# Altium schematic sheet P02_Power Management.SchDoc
size 386 x 246 mm
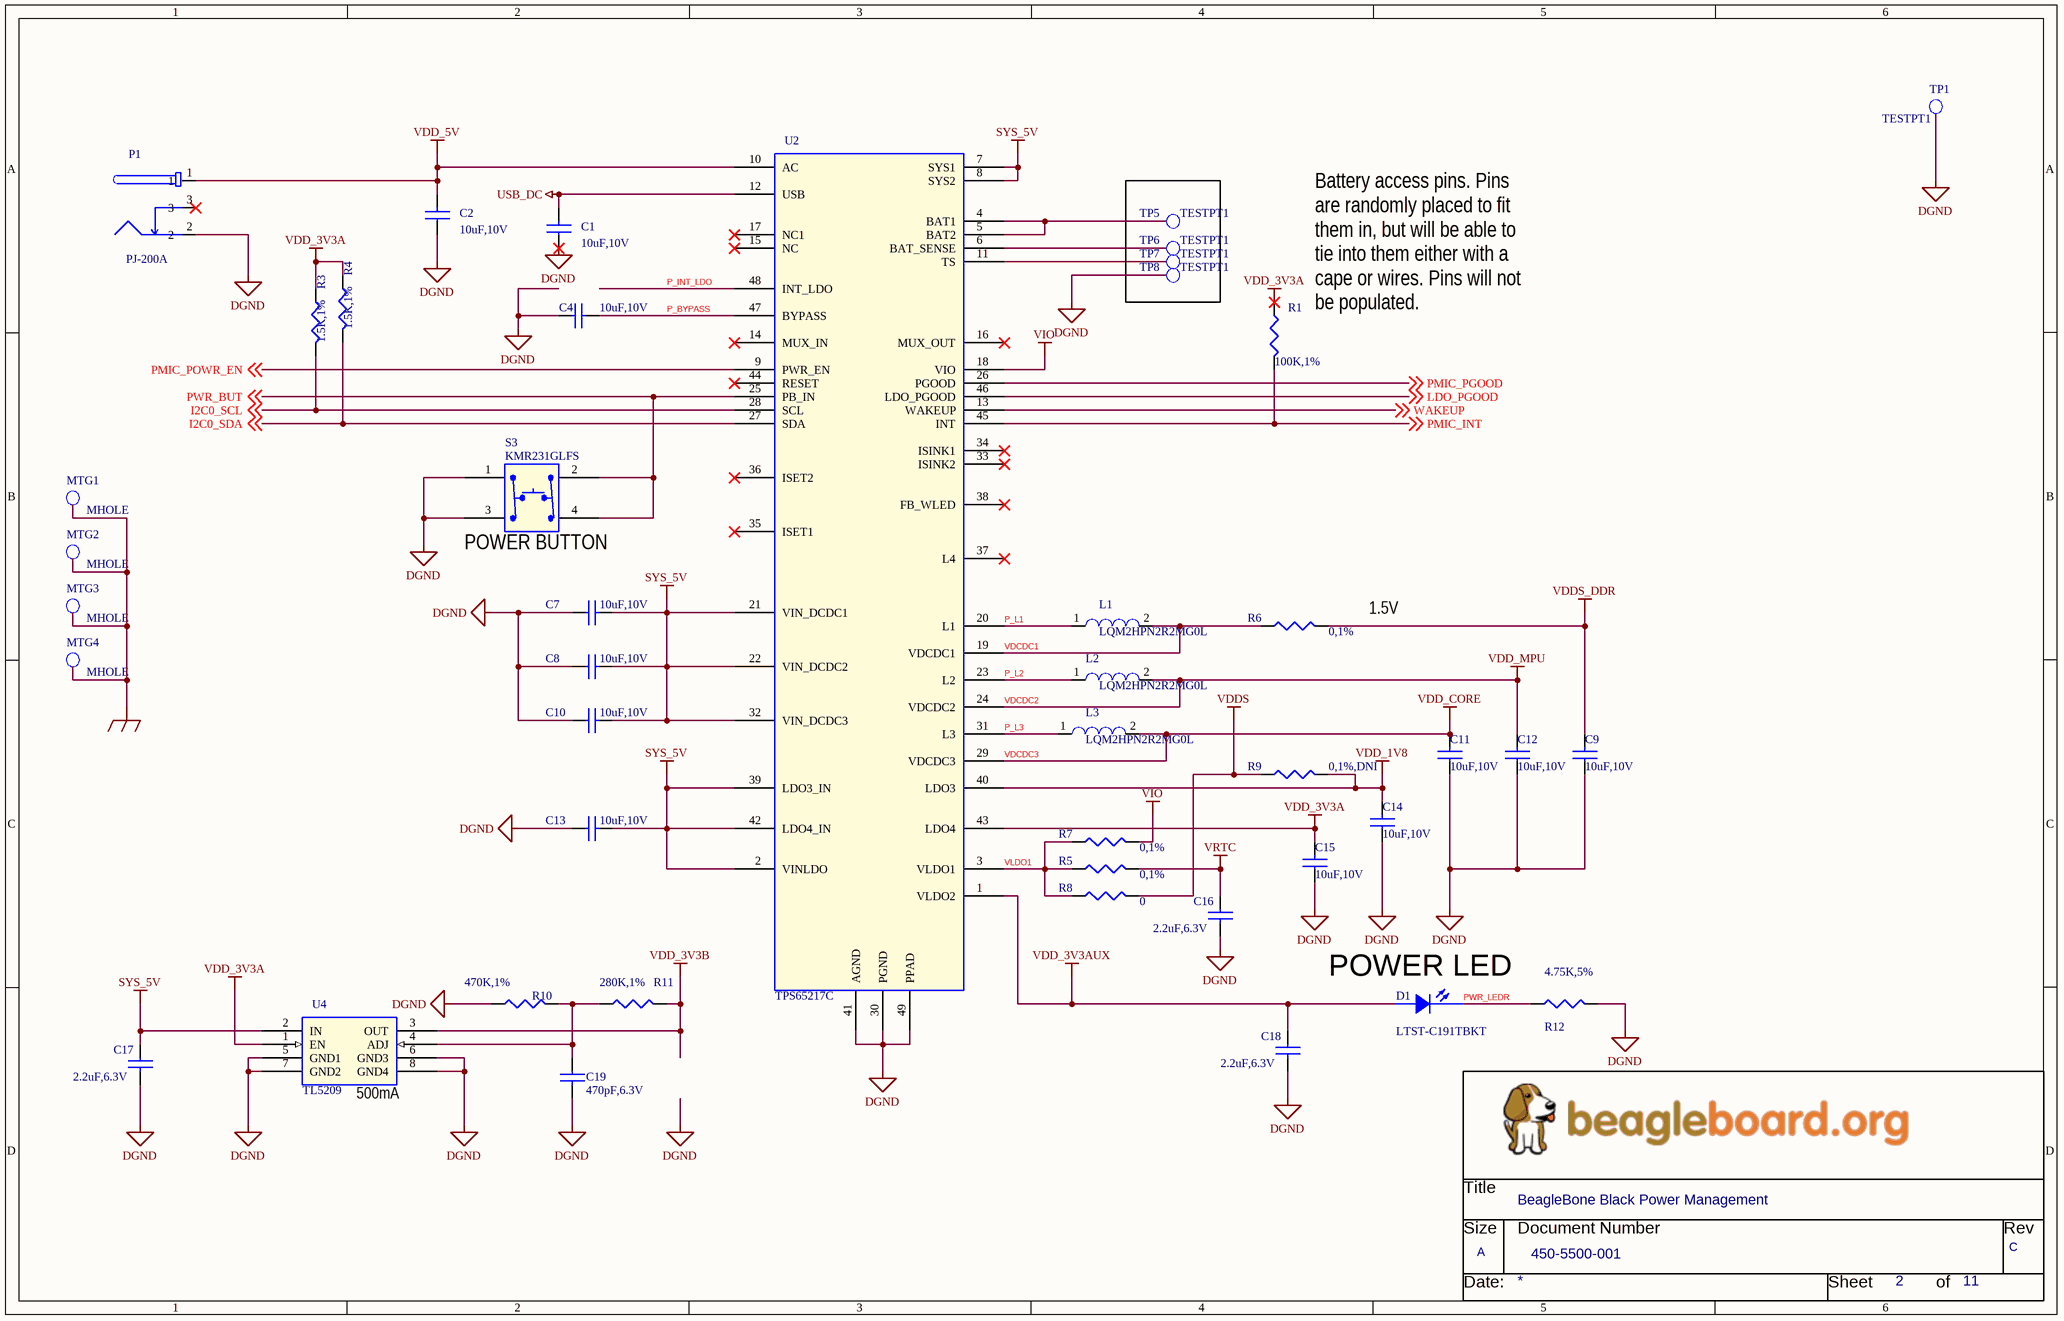
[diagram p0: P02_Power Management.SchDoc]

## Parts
*  Page Count: 11  Page Number: 2  Page Size: A  Title: BeagleBone Black Power Management  RevCode: C  Doc: 450-5500-001  (hidden comment: BeagleBoard_org)  (graphical)
C1  10uF,10V  [r402-25rd]
C2  10uF,10V  [r402-25rd]
C4  10uF,10V  [r402-25rd]
C7  10uF,10V  [r402-25rd]
C8  10uF,10V  [r402-25rd]
C9  10uF,10V  [r402-25rd]
C10  10uF,10V  [r402-25rd]
C11  10uF,10V  [r402-25rd]
C12  10uF,10V  [r402-25rd]
C13  10uF,10V  [r402-25rd]
C14  10uF,10V  [r402-25rd]
C15  10uF,10V  [r402-25rd]
C16  2.2uF,6.3V  [402]
C17  2.2uF,6.3V  [402]
C18  2.2uF,6.3V  [402]
C19  470pF,6.3V  [402]
D1  LTST-C191TBKT  [led1206-59x59]
L1  LQM2HPN2R2MG0L  [VLCF5020T]
L2  LQM2HPN2R2MG0L  [VLCF5020T]
L3  LQM2HPN2R2MG0L  [VLCF5020T]
MTG1  MHOLE  [mh230-156]
MTG2  MHOLE  [mh230-156]
MTG3  MHOLE  [mh230-156]
MTG4  MHOLE  [mh230-156]
P1  PJ-200A  [CONN3-PWR-PJ102A]
R1  100K,1%  [402]
R3  1.5K,1%  [402]
R4  1.5K,1%  [402]
R5  0,1%  [402]
R6  0,1%  [402]
R7  0,1%  [402]
R8  0  [402]
R9  0,1%,DNI  [402]
R10  470K,1%  [402]
R11  280K,1%  [402]
R12  4.75K,5%  [402]
S3  KMR231GLFS  [SM-SW-SPST-4-4]
TP1  TESTPT1  [tp1-8040]
TP5  TESTPT1  [tp1-8040]
TP6  TESTPT1  [tp1-8040]
TP7  TESTPT1  [tp1-8040]
TP8  TESTPT1  [tp1-8040]
U2  TPS65217C  [TBD]
U4  TL5209  [SO8-25X75]

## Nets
DGND: C1.1 C2.1 C4.1 C7.1 C8.1 C9.1 C10.1 C11.1 C12.1 C13.1 C14.1 C15.1 C16.2 C17.2 C18.2 C19.2 P1.2 R10.2 R12.1 S3.1(A1) S3.3(A2) TP1.1(TP) TP8.1(TP) U2.30(PGND) U2.41(AGND) U2.49(PPAD) U4.5(GND1) U4.6(GND3) U4.7(GND2) U4.8(GND4)
GND_EARTH: MTG1.1(TP) MTG2.1(TP) MTG3.1(TP) MTG4.1(TP)
SYS_5V: C7.2 C8.2 C10.2 C13.2 C17.1 U2.2(VINLDO) U2.7(SYS1) U2.8(SYS2) U2.21(VIN_DCDC1) U2.22(VIN_DCDC2) U2.32(VIN_DCDC3) U2.39(LDO3_IN) U2.42(LDO4_IN) U4.2(IN)
USB_DC: C1.2 U2.12(USB)
VDCDC2: C12.2 L2.2 U2.24(VDCDC2)  [also labelled VDD_MPU]
VDCDC3: C11.2 L3.2 U2.29(VDCDC3)  [also labelled VDD_CORE]
VDD_1V8: C14.2 R9.2 U2.40(LDO3)
VDD_3V3A: C15.2 R1.1 R3.1 R4.1 U2.43(LDO4) U4.1(EN)
VDD_3V3AUX: C18.1 D1.2(A) U2.1(VLDO2)
VDD_3V3B: R11.1 U4.3(OUT)
VDD_5V: C2.2 P1.1 U2.10(AC)
VDDS: R8.2 R9.1
VDDS_DDR: C9.2 R6.2
VIO: R7.2 U2.18(VIO)
VRTC: C16.1 R5.2
I2C0_SCL: R3.2 U2.28(SCL) ; off-sheet I2C0_SCL
I2C0_SDA: R4.2 U2.27(SDA) ; off-sheet I2C0_SDA
LDO_PGOOD: U2.46(LDO_PGOOD) ; off-sheet LDO_PGOOD
P_BYPASS: C4.2 U2.47(BYPASS)
P_INT_LDO: U2.48(INT_LDO)
P_L1: L1.1 U2.20(L1)
P_L2: L2.1 U2.23(L2)
P_L3: L3.1 U2.31(L3)
PMIC_INT: R1.2 U2.45(INT) ; off-sheet PMIC_INT
PMIC_PGOOD: U2.26(PGOOD) ; off-sheet PMIC_PGOOD
PMIC_POWR_EN: U2.9(PWR_EN) ; off-sheet PMIC_POWR_EN
PWR_BUT: S3.2(B1) S3.4(B2) U2.25(PB_IN) ; off-sheet PWR_BUT
PWR_LEDR: D1.1(C) R12.2
VDCDC1: L1.2 R6.1 U2.19(VDCDC1)
VLDO1: R5.1 R7.1 R8.1 U2.3(VLDO1)
WAKEUP: U2.13(WAKEUP) ; off-sheet WAKEUP
NetC19_1: C19.1 R10.1 R11.2 U4.4(ADJ)
NetTP5_1: TP5.1(TP) U2.4(BAT1) U2.5(BAT2)
NetTP6_1: TP6.1(TP) U2.6(BAT_SENSE)
NetTP7_1: TP7.1(TP) U2.11(TS)

Not connected (* = marked no-connect by the designer): P1 3*; U2 14(MUX_IN)* 15(NC)* 16(MUX_OUT)* 17(NC1)* 33(ISINK2)* 34(ISINK1)* 35(ISET1)* 36(ISET2)* 37(L4)* 38(FB_WLED)* 44(RESET)*

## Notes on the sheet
- (near R1) Battery access pins. Pins
  are randomly placed to fit
  them in, but will be able to
  tie into them either with a
  cape or wires. Pins will not
  be populated.
- (near S3) POWER BUTTON
- 1.5V
- (near D1) POWER LED
- (near U4) 500mA

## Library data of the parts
C1 C2 C4 C7-C15 = CAP_10uF_Y5V_10V_10%_0805: Desc: CAP CER 10UF 10V Y5V 0805; PCB Footprint: 805
C16-C18 = CAP_2.2uF_X5R_6.3V_10%_0402: Desc: CAP, CER, X7R, 0402, 50V, 10%, 0.1uF
C19 = CAP_470PF_X7R_25V_10%_0402: Desc: Capacitor 470pF 25V 10% X7R
D1 = LED_LTST-C150GKT_0: TN: 257-0020-000; CLASS: DISCRETE; PCB Footprint: LED_0603
L1-L3 = IND_2.2uH_2.6A_10%_SMD: Inductor 2.2uH smt 2.6A, 58 milliohm; TIIntPartnumber: 1L0025; MfrNum: VLCF5020T-2R2N2R6-3; Mfr: TDK; PartName: 2.2uH10%2.6Asmd; PCB Footprint: smd0.157inx0.157in; Cost10K: 0.37; Cost100: 1.11; Vendor: Digikey
MTG1-MTG4 = MHOLE: PCB Footprint: MTGH200C125D_PL
P1 = Power_Jack
R1 = RES_100K_1/16W_1%_0402: Resistor 100Kohm 1/16W 1% 0402
R3 R4 = RES_1.5K_1/16W_5%_0402_Dup1: RES 1.5K OHM 1/16W 5% 0402 SMD
R5-R9 = RES_4.75K_1/16W_1%_0402: RES 4.75K OHM 1/16W 1% 0402 SMD
R10-R12 = RES_470_1/10W_5%_0402: RES 470 OHM 1/10W 5% 0402 SMD
S3 = SW_KT11P2JM_2: CLASS: DISCRETE; TN: 276-0043-000; PCB Footprint: SW4SMD_63X161LS
TP5-TP8 = TESTPT1: PCB Footprint: TP60C33D
U2 = PWR_TPS65217_2: PCB Footprint: U_48_RSL
U4 = PWR_TLV70233DBV_0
